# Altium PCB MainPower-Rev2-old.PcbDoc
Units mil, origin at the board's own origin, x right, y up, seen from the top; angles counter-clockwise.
Board outline 11010.03 x 11010.03 mil, 4 copper layers (Top Layer, Internal Plane 1, Internal Plane 2, Bottom Layer); 40 components, 21 nets, 242 pads, 0 vias.
Unrouted connection lines stored in the file: 175.
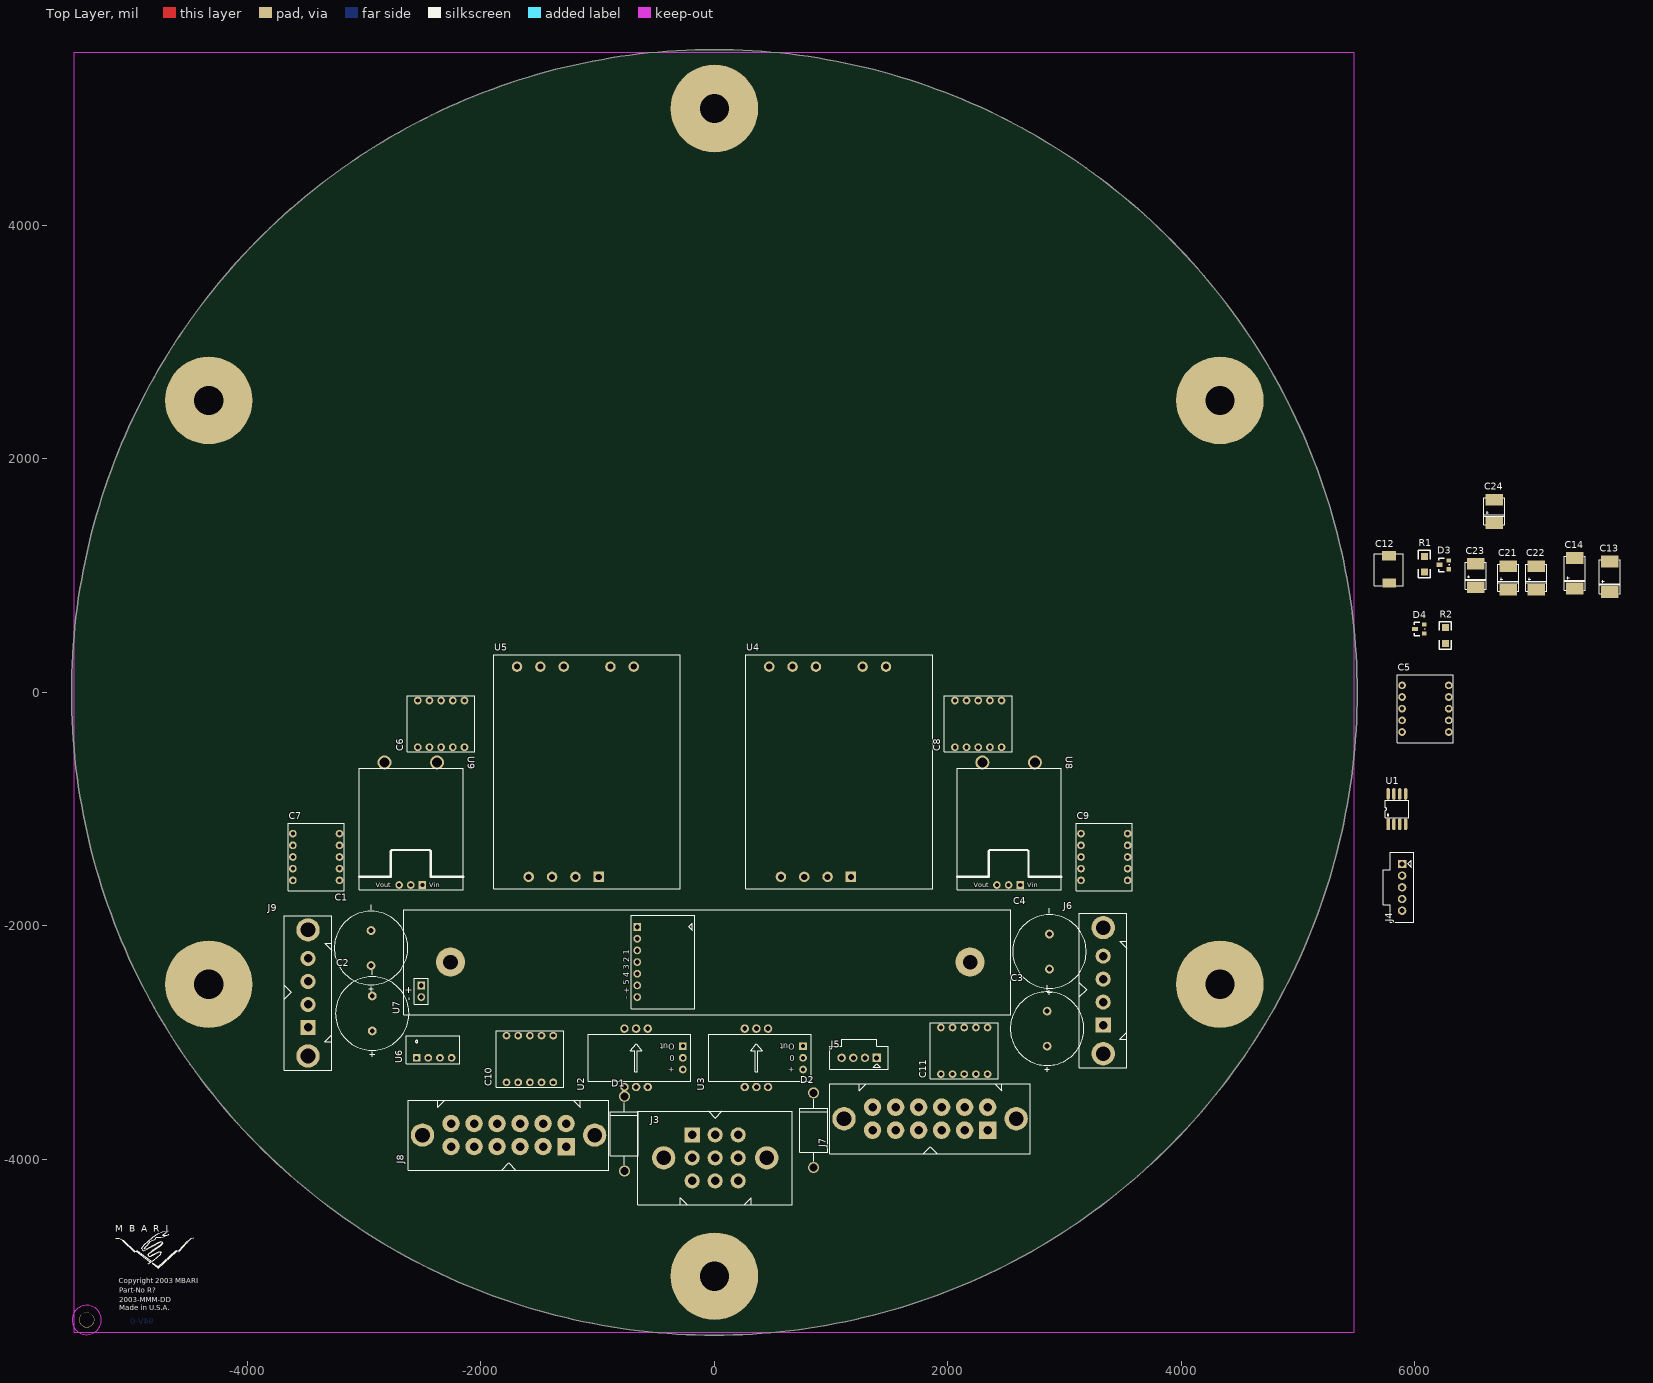
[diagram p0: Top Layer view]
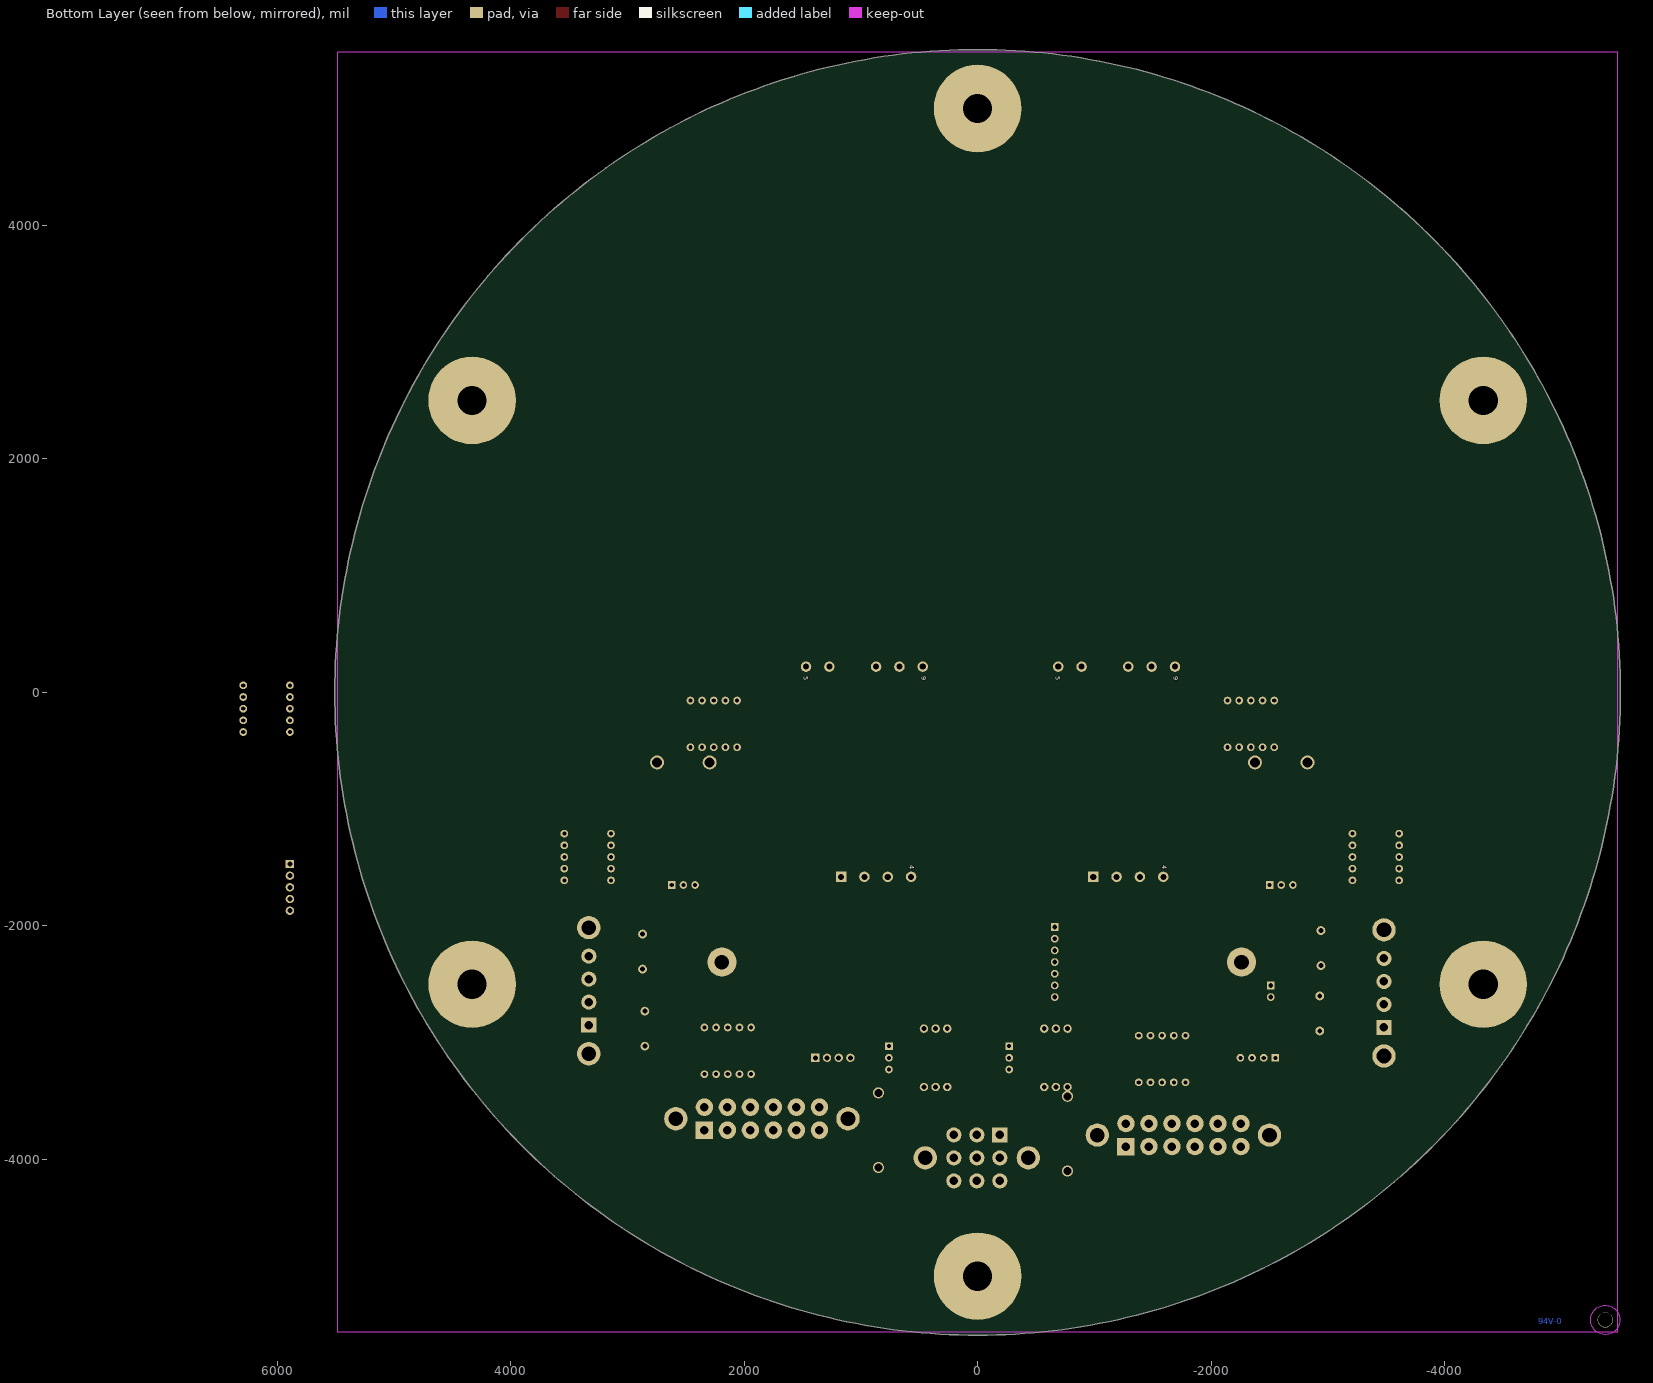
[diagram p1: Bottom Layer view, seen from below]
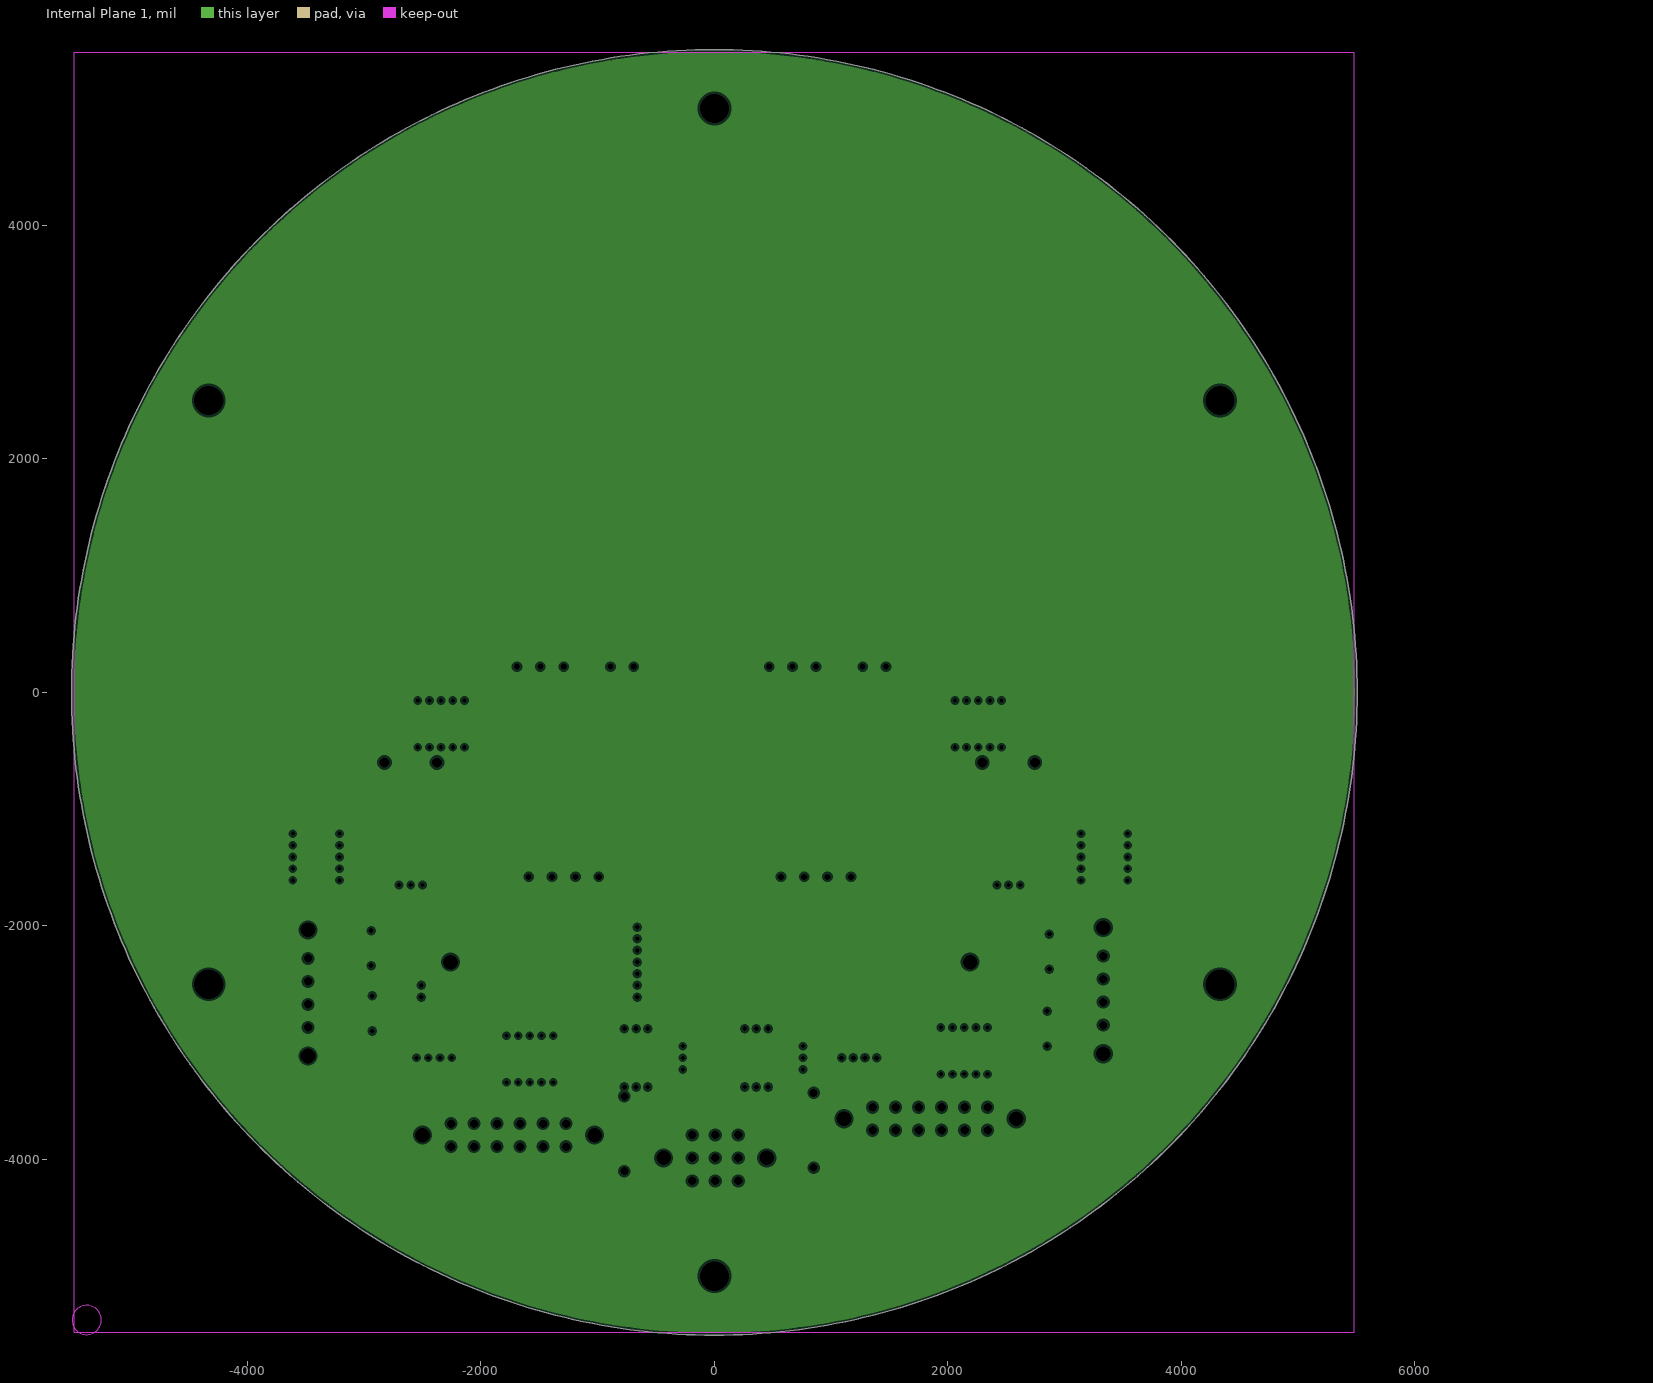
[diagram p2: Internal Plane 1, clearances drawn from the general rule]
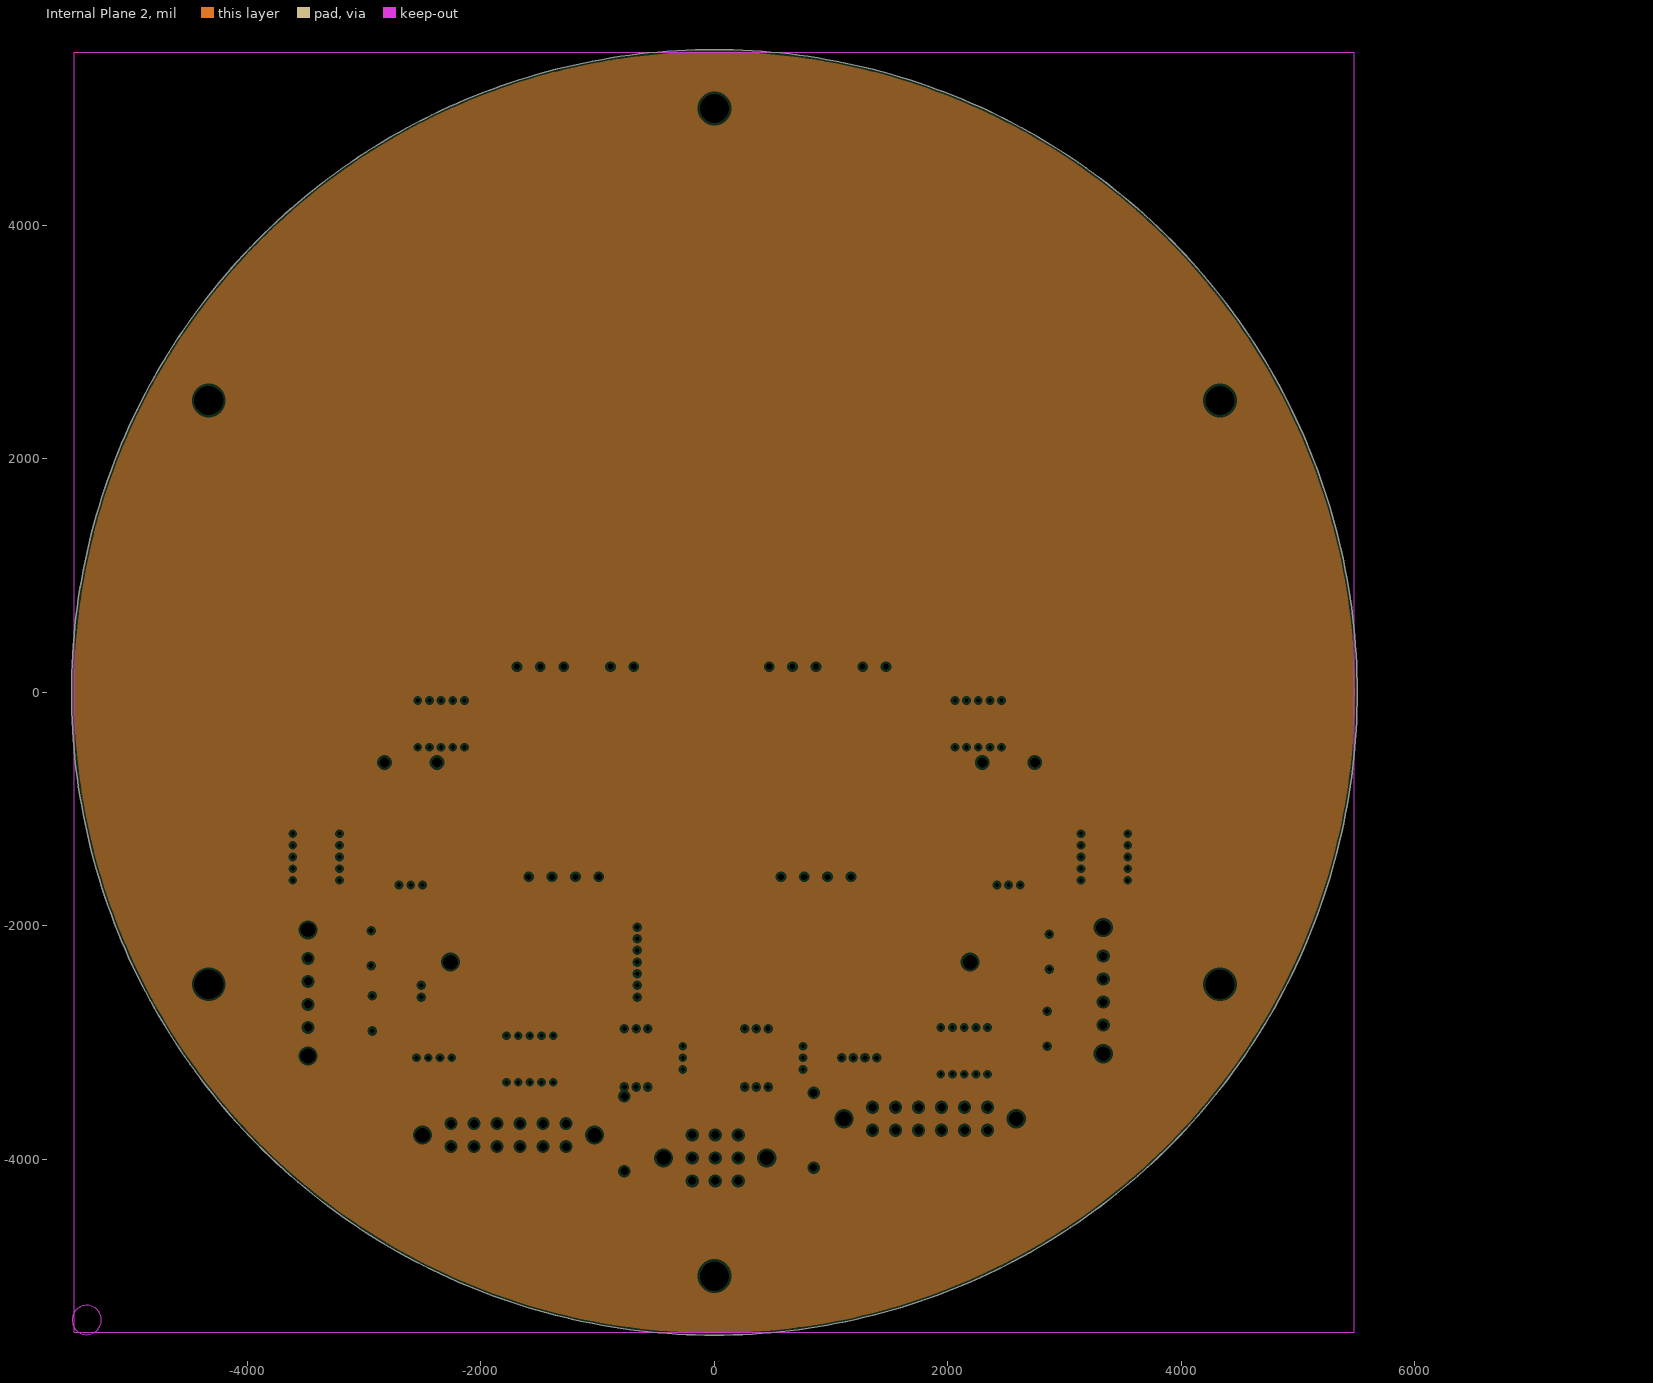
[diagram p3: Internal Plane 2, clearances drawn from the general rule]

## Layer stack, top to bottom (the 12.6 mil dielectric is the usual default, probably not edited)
Top Layer: signal copper 1.4
Dielectric: dielectric 12.6, FR-4, Dk 4.8
Internal Plane 1: plane copper 1.4
Dielectric: dielectric 12.6, FR-4, Dk 4.8
Internal Plane 2: plane copper 1.4
Dielectric: dielectric 12.6, FR-4, Dk 4.8
Bottom Layer: signal copper 1.4

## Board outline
0,-5505.02 cw(c0,0) -5505.02,0 cw(c0,0) 0,5505.01 cw(c0,0) 5505.01,0 cw(c0,0)

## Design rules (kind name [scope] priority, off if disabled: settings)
Clearance [All] p1: gap=13
ComponentClearance [All] p1: gap=10 collisioncheckmode=0
FanoutControl Fanout_Small [(CompPinCount < 5)] p1: bgadir=Out bgaviamode=Centered fanoutstyle=Auto fanoutdirection=OutThenIn viagrid=1 // Fanout_Small (Default Rule)
FanoutControl Fanout_Default [All] p2: bgadir=Out bgaviamode=Centered fanoutstyle=Auto fanoutdirection=Alternating viagrid=1 // Fanout_Default (Default Rule)
FanoutControl Fanout_BGA [IsBGA] p4: bgadir=Out bgaviamode=Centered fanoutstyle=Auto fanoutdirection=Alternating viagrid=1 // Fanout_BGA (Default Rule)
FanoutControl Fanout_LCC [IsLCC] p5: bgadir=Out bgaviamode=Centered fanoutstyle=Auto fanoutdirection=Alternating viagrid=1 // Fanout_LCC (Default Rule)
HoleSize [All] p1: absolutevalues=TRUE maxlimit=152 minlimit=1 maxpercent=80.000 minpercent=20.000
PlaneClearance [All] p1: clearance=20
PlaneConnect [All] p1: planeconnectstyle=Relief reliefexpansion=20 reliefentries=4 reliefconductorwidth=10 reliefairgap=10
PolygonConnect [All] p1: connectstyle=Relief reliefconductorwidth=10 reliefentries=4 polygonreliefangle="90 Angle"
RoutingLayers [All] p1: top layer=Horizontal bottom layer=Vertical
RoutingVias [All] p1: holewidth=35 width=52 viastyle="Through Hole" minholewidth=28 minwidth=32 maxholewidth=86 maxwidth=72
SolderMaskExpansion [All] p1: expansion=4
TestPointUsage [All] p1: valid=0 allowmultiple=FALSE
Testpoint [All] p1: side=15 testpointundercomponent=TRUE minsize=40 maxsize=100 preferedsize=60 minholesize=0 maxholesize=40 preferedholesize=32 testpointgrid=1 style=1023 order=1234567890
Width [All] p1: maxlimit=250 minlimit=8 preferedwidth=12 toplayer_prefwidth=10 bottomlayer_prefwidth=10 minimp=50.000000 maximp=50.000000 favimp=50.000000
9 further rules are at their usual default settings.

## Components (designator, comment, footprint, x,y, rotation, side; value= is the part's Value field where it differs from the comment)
C1 "1000uF" RAD0.3L_0.63D -2940,-2340 r90 top
C2 "1000uF" RAD0.3L_0.63D -2930,-2900 r90 top
C3 "1000uF" RAD0.3L_0.63D 2850,-3030 r90 top
C4 "1000uF" RAD0.3L_0.63D 2870,-2370 r90 top
C5 "10uF" CAPSTICK-CS4-5 5890,-340 r90 top
C6 "10uF" CAPSTICK-CS4-5 -2140,-470 r180 top
C7 "10uF" CAPSTICK-CS4-5 -3610,-1610 r90 top
C8 "10uF" CAPSTICK-CS4-5 2460,-470 r180 top
C9 "10uF" CAPSTICK-CS4-5 3140,-1610 r90 top
C10 "10uF" CAPSTICK-CS4-5 -1380,-3340 r180 top
C11 "10uF" CAPSTICK-CS4-5 2340,-3270 r180 top
C12 "100pF,2kV" ECK 5760,930 r90 top
C13 "150uF,10V" 7343pol 7670,860 r90 top
C14 "47uF,16V" 7343pol 7370,890 r90 top
C21 "33uF,16V" 6032pol 6800,880 r90 top
C22 "33uF,16V" 6032pol 7040,880 r90 top
C23 "33uF,16V" 6032pol 6520,900 r90 top
C24 "33uF,16V" 6032pol 6680,1450 r90 top
D1 "1N5365B" DO-201AD -770,-4100 r90 top
D2 "1N5401" DO-201AD 850,-4070 r90 top
D3 "5V LED" SOT-23 6290,1130 r90 top
D4 "12V LED" SOT-23 6080,580 r90 top
J3 "Raw Bus In/Out" PLC09 -190,-3790 r0 top
J4 "Temp" CGRID5 5890,-1470 r90 top
J5 "CurSense" CGRID4 1390,-3130 r0 top
J6 "5V Power" PLA04 3330,-2850 r90 top
J7 "12V POWER" PLB12 2340,-3750 r180 top
J8 "Raw Bus Power" PLB12 -1270,-3890 r180 top
J9 "Kearfott/ParoSci" PLA04 -3480,-2870 r90 top
R1 "3.3K" 1206 6080,1030 r90 top
R2 "10K" 1206 6260,420 r90 top
U1 "DS1620S" SOIC-8 5770,-1130 r90 top
U2 "LTS6-NP" LTS6-NP -200,-3330 r180 top
U3 "LTS6-NP" LTS6-NP 830,-3330 r180 top
U4 "UHE-5/5000-Q12" DATEL-UHE 1170,-1580 r90 top
U5 "UHE-12/2500-D24" DATEL-UHE -990,-1580 r90 top
U6 "NKE1209S" NKEDCDC -2550,-3130 r90 top
U7 "ST411" ST411 -2660,-2310 r90 top
U8 "78HT305HC" PT78ST-HORIZ 2520,-1650 r0 top
U9 "78ST133HC" PT78ST-HORIZ -2600,-1650 r0 top (schematic designator PS1)

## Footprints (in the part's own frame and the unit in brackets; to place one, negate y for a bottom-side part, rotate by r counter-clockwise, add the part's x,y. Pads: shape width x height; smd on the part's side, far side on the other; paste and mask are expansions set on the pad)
1206 [mil]
  rect 60x60 smd: 1(0,0) 2(135,0)
  silkscreen extent -50,-50 185,50
6032pol [mil]
  rect 100x150 smd: 1(0,0) 2(200,0)
  silkscreen extent -15,-90 215,90
7343pol [mil]
  rect 100x150 smd: 1(0,0) 2(260,0)
  silkscreen extent -15,-90 275,90
CAPSTICK-CS4-5 [mil]
  round 66 hole 35: 1(0,0) 1(100,0) 1(200,0) 1(300,0) 1(400,0) 2(0,-400) 2(100,-400) 2(200,-400) 2(300,-400) 2(400,-400)
  silkscreen extent -90,-440 490,40
CGRID4 [mil]
  rect 72x72 hole 42: 1(0,0)
  round 72 hole 42: 2(-100,0) 3(-200,0) 4(-300,0)
  silkscreen extent -400,-100 100,160
CGRID5 [mil]
  rect 72x72 hole 42: 1(0,0)
  round 72 hole 42: 2(-100,0) 3(-200,0) 4(-300,0) 5(-400,0)
  silkscreen extent -500,-100 100,160
DATEL-UHE [mil] "Datel UHE 1.6x2.0 DC/DC Converter"
  rect 90x90 hole 52: 1(0,0)
  round 90 hole 52: 2(0,200) 3(0,400) 4(0,600) 5(1800,-300) 6(1800,-100) 7(1800,300) 8(1800,500) 9(1800,700)
  silkscreen extent -100,-700 1900,900
DO-201AD [mil]
  round 95 hole 67: 1(0,0) 2(640,0)
  silkscreen extent 55,-120 585,120
ECK [mm]
  rect 2x3 smd: 1(0.15,-0.5) 2(6.075,-0.475)
  silkscreen extent -0.4,-3.6 6.5,2.7
LTS6-NP [mil]
  round 72 hole 42: 1(370,-450) 2(470,-450) 3(570,-450) 4(570,50) 5(470,50) 6(370,50)
  rect 66x66 hole 35: a(70,-300)
  round 66 hole 35: b(70,-200) c(70,-100)
  silkscreen extent 0,-400 880,0
NKEDCDC [mil]
  rect 66x66 hole 35: 1(0,0)
  round 66 hole 35: 2(0,-100) 3(0,-200) 4(0,-300)
  silkscreen extent -50,-370 190,90
PLA04 [mil] "Positronic 1x4 pin"
  round 200 hole 125: 0(-244.5,0) 0(835.5,0)
  rect 130x130 hole 73: 1(0,0)
  round 130 hole 73: 2(197,0) 3(394,0) 4(591,0)
  silkscreen extent -366,-204 956,204
PLB12 [mil] "Positronic 2x6 pin"
  round 200 hole 125: 0(-244.5,-98.5) 0(1229.5,-98.5)
  rect 150x150 hole 73: 1(0,0)
  round 150 hole 73: 2(197,0) 3(394,0) 4(591,0) 5(788,0) 6(985,0) 7(0,-197) 8(197,-197) 9(394,-197) 10(591,-197) 11(788,-197) 12(985,-197)
  silkscreen extent -366,-399 1350,202
PLC09 [mil] "Positronic 3x3 pins"
  round 200 hole 125: 0(-244.5,-197) 0(638.5,-197)
  rect 130x130 hole 73: 1(0,0)
  round 130 hole 73: 2(197,0) 3(394,0) 4(0,-197) 5(197,-197) 6(394,-197) 7(0,-394) 8(197,-394) 9(394,-394)
  silkscreen extent -465,-598 859,205
PT78ST-HORIZ [mil]
  round 120 hole 86: 0(-225,1050) 0(225,1050)
  rect 65x65 hole 35: 1(100,0)
  round 65 hole 35: 2(0,0) 3(-100,0)
  silkscreen extent -440,-40 450,1000
RAD0.3L_0.63D [mil]
  round 75 hole 42: 1(0,0) 2(300,0)
  silkscreen extent -220,-315 520,315
SOIC-8 [mil]
  rect 100x30 smd: 1(0,0)
  oval 100x30 smd: 2(0,-50) 3(0,-100) 4(0,-150) 5(260,-150) 6(260,-100) 7(260,-50) 8(260,0)
  silkscreen extent 55,-175 205,25
SOT-23 [mil]
  rect 36x36 smd: 1(0,0) 2(-75,0)
  rect 36x50 smd: 3(-37,80)
  silkscreen extent -95,-5 20,85
ST411 [mil]
  round 250 hole 125: 00(0,-400) 0(0,-4850)
  rect 66x66 hole 42: 01(-200,-150) 1(300,-2000)
  round 66 hole 42: 02(-300,-150) 2(200,-2000) 3(100,-2000) 4(0,-2000) 5(-100,-2000) 6(-200,-2000) 7(-300,-2000)
  silkscreen extent -450,-5200 450,0

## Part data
C1 C2 C3 C4: library part "CAPACITOR POL", "Capacitor"
C5 C6 C7 C8 C9 C10 C11 C12 C13 C14 C21 C22 C23 C24: library part CAPACITOR, "Capacitor"
D1: library part ZENER3, "Zener Diode"
D2: library part DIODE_S, "Diode"
D3 D4: library part LED, "LED"
J3: library part CON3X3, "9 pin connector"
J4: library part CON5, "Connector"
J5 J6 J9: library part CON4, "Connector"
J7 J8: library part CON12-PLB, "Positronic 12 pin connector"
R1 R2: library part RESISTOR, "Resistor"
U1: library part DS1620, "DallasSemi Digital Thermometer and Thermostat"
U2 U3: "Current Transducer"
U4 U5: library part UHE, "Datel UHE DC->DC Isolated Converter"
U6: library part NKE1209S-BW, "DC->DC Isol Converter 12->9VDC"
U7: "Novatech Strobe Beacon"
U8: library part PT78STXXX, "Power Trends Switching Reg 5V, 3A"
U9: library part PT78STXXX, "Power Trends Switching Reg"

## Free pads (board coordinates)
  round 130 hole 125: 0(-5375,-5375)
  round 750 hole 250: 0(0,5000) 1(0,-5000) 2(-4330,-2500) 2(-4330,2500) 3(4330,-2500) 3(4330,2500)

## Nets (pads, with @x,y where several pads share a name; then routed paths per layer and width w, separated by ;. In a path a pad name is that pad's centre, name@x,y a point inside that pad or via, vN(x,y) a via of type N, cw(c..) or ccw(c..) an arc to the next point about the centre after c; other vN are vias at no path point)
5V: C13.1 J6.1 J6.3 R1.1 U4.5 U4.6
9V: C21.1 J9.3 U6.4
9VGND: C21.2 J9.4 U6.3
12V: C14.1 C22.1 C23.1 C24.1 J7.1 J7.2 J7.3 J7.4 J7.5 J7.6 R2.1 U5.5 U5.6 U6.2 U8.1 U9.1
AN0VJ3: J5.4 U2.b U3.b
AN5VJ3: J5.1 U2.c U3.c
BUS+: D1.2 D2.2 J3.1 J3.2 U2.4 U2.5 U2.6 U3.4 U3.5 U3.6
BUS-: C1.2 C2.2 C3.2 C4.2 C5.2 C6.2 C7.2 C8.2 C9.2 C10.2 C11.2 C12.2 D1.1 D2.1 J3.4 J3.5 J3.6 J8.7 J8.8 J8.9 J8.10 J8.11 J8.12 J9.2 U4.2 U5.2
ELEC+: C2.1 C3.1 C4.1 C6.1 C7.1 C8.1 C9.1 C10.1 C11.1 J8.1 J8.2 J8.3 J8.4 J8.5 J8.6 J9.1 U3.1 U3.2 U3.3 U4.1 U5.1
ELECCUR: J5.3 U3.a
GND: C13.2 C14.2 C22.2 C23.2 C24.2 D3.3 D4.3 J6.2 J6.4 J7.7 J7.8 J7.9 J7.10 J7.11 J7.12 U4.7 U4.8 U5.7 U5.8 U6.1 U8.2 U9.2
LOCO+: C1.1 C5.1 J3.3 U2.1 U2.2 U2.3
LOCOCUR: J5.2 U2.a
NetD3_2: D3.2 R1.2
NetD4_2: D4.2 R2.2
NetJ4_1: J4.1 U1.4
NetJ4_2: J4.2 U1.8
NetJ4_3: J4.3 U1.1
NetJ4_4: J4.4 U1.2
NetJ4_5: J4.5 U1.3
SHIELD: C12.1 J3.7 J3.8 J3.9
pads on no net: D3.1 D4.1 J3.0 J6.0 J7.0 J8.0 J9.0 U1.5 U1.6 U1.7 U4.3 U4.4 U4.9 U5.3 U5.4 U5.9 U7.0 U7.00 U7.01 U7.1 U7.02 U7.2 U7.3 U7.4 U7.5 U7.6 U7.7 U8.0 U8.3 U9.0 U9.3

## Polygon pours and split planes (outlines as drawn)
no net on Internal Plane 1 (split plane): 0,-5485 cw(c0,0) -5485,0 cw(c0,0) 0,5485 cw(c0,0) 5485,0 cw(c0,0)
no net on Internal Plane 2 (split plane): 0,-5485 cw(c0,0) -5485,0 cw(c0,0) 0,5485 cw(c0,0) 5485,0 cw(c0,0)

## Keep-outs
Keep-Out Layer:
  circle w10: c-5375,-5375 r125
  lines w10: -5480,-5480 5480,-5480 5480,5480 -5480,5480 -5480,-5480
  text ".GKO" at 12740,-6040 h90

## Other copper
Top Layer:
  text ".GTL" at 12740,-6040 h90
Bottom Layer:
  text "94V-0" at -4802.93,-5411.21 h50
  text ".GBL" at 12740,-6040 h90

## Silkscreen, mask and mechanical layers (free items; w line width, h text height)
Top Overlay:
  lines w10: -5127,-4674 -5095,-4676 -5064,-4694 -4963,-4785 -4950,-4781 -4943,-4782 -4829,-4869 ; -5072,-4692 -4969,-4789 ; -4964,-4792 -4949,-4788 -4834,-4876 ; -4847,-4892 -4801,-4865 -4742,-4811 -4739,-4804 -4739,-4794 -4741,-4791 -4747,-4790 -4754,-4790 ; -4816,-4890 -4769,-4927 ; -4812,-4883 -4764,-4921 -4612,-4783 -4603,-4779 -4589,-4784 -4510,-4698 -4507,-4703 -4478,-4677 -4458,-4673 ; -4740,-4805 -4740,-4797 -4742,-4793 -4747,-4791 -4754,-4790 ; -4606,-4787 -4591,-4792 ; -4584,-4788 -4519,-4715 ; -4516,-4718 -4510,-4709 ; -4754,-4790 -4761,-4793 -4804,-4813 -4821,-4824 -4844,-4828 -4848,-4823 -4847,-4811 -4809,-4779 -4741,-4732 -4730,-4716 -4734,-4705 -4740,-4703 -4764,-4709 -4800,-4729 -4848,-4757 -4878,-4767 -4882,-4763 -4871,-4748 -4853,-4733 -4831,-4703 -4813,-4693 -4798,-4686 -4785,-4678 -4778,-4667 -4743,-4667 -4720,-4662 -4704,-4656 -4688,-4651 -4671,-4641 -4676,-4645 -4705,-4650 -4722,-4650 -4679,-4611 -4728,-4619 -4767,-4637 -4810,-4665 -4849,-4699 -4877,-4726 -4899,-4751 -4903,-4759 -4904,-4765 -4901,-4772 -4896,-4776 -4888,-4781 -4878,-4780 -4750,-4710 -4740,-4707 -4733,-4707 -4729,-4709 -4727,-4713 -4725,-4718 -4728,-4725 -4736,-4734 -4831,-4799 -4842,-4807 -4846,-4815 -4847,-4821 -4843,-4828 -4836,-4830 -4828,-4828 -4754,-4790 ; -4763,-4932 -4604,-4787 -4763,-4932
  text "M  B  A  R  I" at -5130,-4620 h55
  text "Copyright 2003 MBARI" at -5100,-5060 h45
  text "Part-No R?" at -5095,-5143.32 h45
  text "2003-MMM-DD" at -5095,-5223.32 h45
  text "Made in U.S.A." at -5095,-5293.32 h45
  text ".GTO" at 12740,-6040 h90
Bottom Overlay:
  text ".GBO" at 12750,-6040 h90
Top Solder:
  text ".GTS" at 12740,-6040 h90
Bottom Solder:
  text ".GBS" at 12740,-6040 h90
Drill Guide:
  text ".GG1" at 9950,-6040 h90
Mechanical 4:
  circle w10: c-50,-1850 r4550.27
  circle w10: c0,0 r5500
  rectangle: -3900,-4250 3800,600
  lines w10: -5500,-5500 5500,-5500 5500,5500 -5500,5500 -5500,-5500
Mechanical 16:
  lines w5: -6300,-3700 -6100,-3700 ; -6300,-1300 -6100,-1300 ; -6300,1100 -6100,1100 ; -6300,3500 -6100,3500 ; -6300,5900 -6100,5900 ; -3900,-6300 -3900,-6100 ; -3900,8100 -3900,8300 ; -1500,-6300 -1500,-6100 ; -1500,8100 -1500,8300 ; 900,-6300 900,-6100 ; 900,8100 900,8300 ; 3300,-6300 3300,-6100 ; 3300,8100 3300,8300 ; 5600,-6100 13100,-6100 ; 5700,-6300 5700,-6100 ; 5700,8100 5700,8300 ; 7200,-5500 13100,-5500 ; 8100,-6300 8100,-6100 ; 8100,8100 8100,8300 ; 8600,-5800 13100,-5800 ; 8600,-5200 10100,-5200 ; 10100,-6100 10100,-5500 10100,-4900 ; 10500,-6300 10500,-6100 ; 10500,8100 10500,8300 ; 12200,-6100 12200,-5500 ; 13100,-4900 10100,-4900 ; 13100,-3700 13300,-3700 ; 13100,-1300 13300,-1300 ; 13100,1100 13300,1100 ; 13100,3500 13300,3500 ; 13100,5900 13300,5900 ; 8600,-4900 7200,-4900 7200,-6100 8600,-6100 8600,-4900 ; 8600,-4900 10100,-4900 ; 13100,-6100 -6100,-6100 -6100,8100 13100,8100 13100,-6100 ; -6300,-6300 -6300,8300 13300,8300 13300,-6300 -6300,-6300
  lines w10: 7533,-5054 7565,-5056 7596,-5074 7697,-5165 7710,-5161 7717,-5162 7831,-5249 ; 7588,-5072 7691,-5169 ; 7696,-5172 7711,-5168 7826,-5256 ; 7813,-5272 7859,-5245 7918,-5191 7921,-5184 7921,-5174 7919,-5171 7913,-5170 7906,-5170 ; 7844,-5270 7891,-5307 ; 7848,-5263 7896,-5301 8048,-5163 8057,-5159 8071,-5164 8150,-5078 8153,-5083 8182,-5057 8202,-5053 ; 7920,-5185 7920,-5177 7918,-5173 7913,-5171 7906,-5170 ; 8054,-5167 8069,-5172 ; 8076,-5168 8141,-5095 ; 8144,-5098 8150,-5089 ; 7906,-5170 7899,-5173 7856,-5193 7839,-5204 7816,-5208 7812,-5203 7813,-5191 7851,-5159 7919,-5112 7930,-5096 7926,-5085 7920,-5083 7896,-5089 7860,-5109 7812,-5137 7782,-5147 7778,-5143 7789,-5128 7807,-5113 7829,-5083 7847,-5073 7862,-5066 7875,-5058 7882,-5047 7917,-5047 7940,-5042 7956,-5036 7972,-5031 7989,-5021 7984,-5025 7955,-5030 7938,-5030 7981,-4991 7932,-4999 7893,-5017 7850,-5045 7811,-5079 7783,-5106 7761,-5131 7757,-5139 7756,-5145 7759,-5152 7764,-5156 7772,-5161 7782,-5160 7910,-5090 7920,-5087 7927,-5087 7931,-5089 7933,-5093 7935,-5098 7932,-5105 7924,-5114 7829,-5179 7818,-5187 7814,-5195 7813,-5201 7817,-5208 7824,-5210 7832,-5208 7906,-5170 ; 7897,-5312 8056,-5167 7897,-5312
  text "7" at 9370,8170 h70
  text "8" at 11740,8170 h70
  text "1" at -4980,8160 h70
  text "2" at -2700,8160 h70
  text "3" at -340,8160 h70
  text "4" at 2010,8160 h70
  text "5" at 4470,8160 h70
  text "6" at 6840,8160 h70
  text "A" at -6230,7040 h70
  text "A" at 13170,7040 h70
  text "B" at -6240,4630 h70
  text "B" at 13160,4630 h70
  text "C" at -6220,2360 h70
  text "C" at 13180,2360 h70
  text "D" at -6240,-90 h70
  text "D" at 13160,-90 h70
  text "E" at -6220,-2600 h70
  text "E" at 13180,-2600 h70
  text "M  B  A  R  I" at 7530,-5000 h55
  text "ENGINEER:" at 8650,-5000 h45
  text "TITLE:" at 10150,-5000 h45
  text "Mark Sibenac" at 9160,-5030 h70
  text "F" at -6240,-5050 h70
  text "F" at 13160,-5050 h70
  text "Title I" at 10500,-5120 h90
  text "1 831 775 2028" at 9150,-5170 h60
  text "PCB DESIGNER:" at 8650,-5295 h45
  text "Title II" at 10520,-5340 h90
  text "Copyright      2003" at 7380,-5350 h60
  text "Monterey Bay Aquarium Research Institute" at 7250,-5460 h45
  text "DATE:" at 8650,-5600 h45
  text "PART NO.:" at 10150,-5600 h45
  text "REV:" at 12250,-5600 h45
  text ".PRINT_DATE" at 8700,-5720 h70
  text "1" at 12530,-5720 h90
  text "Part Number" at 10510,-5730 h60
  text "M.B.A.R.I." at 7280,-5740 h100
  text "7700 Sandholdt Rd." at 7270,-5840 h60
  text "FILE NAME:" at 8650,-5900 h45
  text "DWG NO:" at 10150,-5900 h45
  text "GERBER:" at 12250,-5900 h45
  text "Moss Landing, CA 95039" at 7270,-5950 h60
  text "DWG Number" at 10510,-5990 h60
  text ".PCB_FILE_NAME_NO_PATH" at 8700,-6020 h70
  text ".GM16" at 12360,-6030 h70
  text "Fax: 1 831 775 1646" at 7270,-6050 h60
  text "7" at 9370,-6230 h70
  text "8" at 11740,-6230 h70
  text "1" at -4980,-6240 h70
  text "2" at -2700,-6240 h70
  text "3" at -340,-6240 h70
  text "4" at 2010,-6240 h70
  text "5" at 4470,-6240 h70
  text "6" at 6840,-6240 h70
Drill Drawing:
  text ".LEGEND" at 4445,-4630 h60
  text "Drill Drawing." at 4425,-4720 h60
  text ".GD1" at 9945,-6040 h90

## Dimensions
-5500,-5500 to 5500,-5500 on Mechanical 4
-5500,5500 to -5500,-5500 on Mechanical 4
-5375,-5375 to -5500,-5500 on Mechanical 4
-5375,-5375 to -5500,-5500 on Mechanical 4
